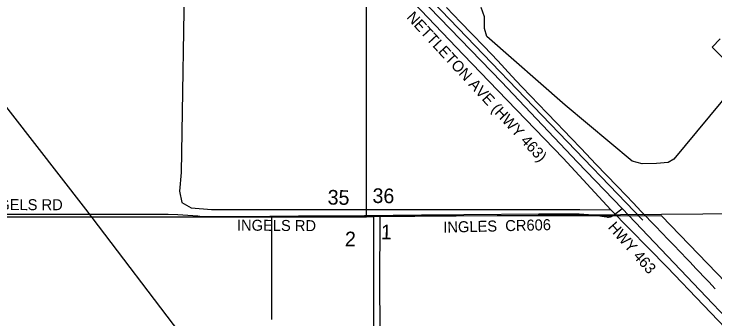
# Model space of a CAD drawing. Extents: x 1670563 to 1761545, y 515755 to 578944.
# Drawn here: x 1717674 to 1722466, y 533025 to 535106 of the extents above; entities that cross this region are included whole.
import ezdxf

# ---------------------------------------------------------------- set-up
doc = ezdxf.new("R2010")
doc.units = 0
for name, color, linetype in [('4_TwnRge', 7, 'Continuous'), ('5_sectionlines', 7, 'Continuous'), ('62_text', 7, 'Continuous'), ('LIMITS', 7, 'Continuous'), ('RR Tracks', 7, 'Continuous'), ('SHP_LINE', 7, 'Continuous'), ('STREETCL', 7, 'Continuous'), ('STRNAMES', 7, 'Continuous')]:
    doc.layers.add(name, color=color, linetype=linetype)

# ---------------------------------------------------------------- blocks, each defined once
blk = doc.blocks.new('CITY_LIMITS02')
at = {"layer": 'LIMITS'}
for p, q in [((1720133.6, 533723.3), (1719433.6, 533721.5)), ((1719433.6, 533721.5), (1719433.6, 533021.5))]:
    blk.add_line(p, q, dxfattribs=at)
for points in [[(1720186.9, 533726.2), (1719433.6, 533721.5)], [(1719433.6, 533721.5), (1719433.6, 533021.5)], [(1722101.2, 533728.6), (1720186.9, 533726.2)], [(1725619.7, 530087.6), (1722101.2, 533728.6)]]:
    blk.add_lwpolyline(points, dxfattribs=at)
blk = doc.blocks.new('RR TRACKS02')
at = {"layer": 'RR Tracks'}
for p, q in [((1720631.5, 535150.1), (1720678.7, 535101)), ((1720678.7, 535101), (1720726.7, 535050.3)), ((1720726.7, 535050.3), (1720803.3, 534970.9)), ((1720803.3, 534970.9), (1720887.3, 534883.9)), ((1720887.3, 534883.9), (1720980.7, 534786)), ((1720980.7, 534786), (1721076.2, 534682.2)), ((1721076.2, 534682.2), (1721143.9, 534612.4)), ((1721143.9, 534612.4), (1721209.1, 534544.3)), ((1721209.1, 534544.3), (1721258.2, 534493.2)), ((1721258.2, 534493.2), (1721319.4, 534429)), ((1721319.4, 534429), (1721381.8, 534364.4)), ((1721381.8, 534364.4), (1721434.4, 534308.8)), ((1721434.4, 534308.8), (1721479.7, 534261.8)), ((1721479.7, 534261.8), (1721550.1, 534187.9)), ((1721550.1, 534187.9), (1721651.7, 534082.3)), ((1721651.7, 534082.3), (1721723.8, 534007.2)), ((1721723.8, 534007.2), (1721796.7, 533931.4)), ((1721796.7, 533931.4), (1721857.7, 533867.3)), ((1721857.7, 533867.3), (1721905.8, 533817.5)), ((1721905.8, 533817.5), (1721962, 533759.4)), ((1721962, 533759.4), (1722062.2, 533655)), ((1722062.2, 533655), (1722100.4, 533614.8)), ((1722100.4, 533614.8), (1722148.2, 533565.7)), ((1722148.2, 533565.7), (1722176.7, 533535.5)), ((1722176.7, 533535.5), (1722234.2, 533475.3)), ((1722234.2, 533475.3), (1722267.9, 533439.9)), ((1722267.9, 533439.9), (1722293, 533413.9)), ((1722293, 533413.9), (1722337.8, 533367.2)), ((1722337.8, 533367.2), (1722360.6, 533344.4)), ((1722360.6, 533344.4), (1722387.2, 533315.1)), ((1722387.2, 533315.1), (1722423.6, 533277.7)), ((1722423.6, 533277.7), (1722467.5, 533231.8))]:
    blk.add_line(p, q, dxfattribs=at)

msp = doc.modelspace()

# ---------------------------------------------------------------- linework, layer by layer
at = {"layer": '4_TwnRge'}
msp.add_lwpolyline([(1714766.6, 533721.4), (1720083.7, 533721.1), (1720133.6, 533723.3), (1725191.1, 533766.2)], dxfattribs=at)
at = {"layer": '5_sectionlines'}
msp.add_line((1720083.7, 533721.1), (1720086.4, 537683), dxfattribs=at)
msp.add_lwpolyline([(1720176.8, 517754.9), (1720182.8, 523040.4), (1720130.2, 528390.8), (1720133.6, 533723.3)], dxfattribs=at)
at = {"layer": 'SHP_LINE'}
for points in [[(1716945, 538927), (1717499, 538359), (1718014, 537823), (1718693, 537111), (1720080, 535667), (1721972, 533700)], [(1716534, 536345), (1716546, 536123), (1716656, 535763), (1716958, 535332), (1717479, 534651), (1718163, 533775), (1718848, 532874), (1719368, 532244), (1719571, 531974), (1719701, 531778), (1719885, 531402), (1720057, 531046)], [(1721755, 533769), (1721429, 534123), (1720982, 534585), (1720746, 534827), (1720310, 535287), (1719979, 535628)], [(1718842, 535542), (1718816, 534025)], [(1722584, 534596), (1722184, 534116), (1722145, 534093), (1722067, 534086), (1721967, 534083), (1721899, 534103), (1721441, 534485), (1720907, 534953), (1720891, 535008), (1720891, 535086), (1720868, 535151)], [(1722502, 534936), (1722447, 534881), (1722577, 534751)], [(1718816, 534025), (1718806, 533897), (1718821, 533820), (1718886, 533784), (1719025, 533771), (1719558, 533773), (1719784, 533772), (1721542, 533772), (1721755, 533769)], [(1721755, 533769), (1722138, 533378), (1723630, 531822), (1724568, 530832), (1725321, 530047), (1726931, 528365), (1727244, 528033), (1727283, 527958), (1727301, 527835), (1727362, 527254), (1727431, 526925), (1727535, 526724), (1727681, 526504), (1728027, 526073), (1728202, 525853), (1728254, 525718), (1728235, 525608)]]:
    msp.add_lwpolyline(points, dxfattribs=at)
at = {"layer": 'STREETCL'}
for points in [[(1717072.9, 538715.7), (1717264.4, 538514.7), (1717510.3, 538264.3), (1717644.4, 538130.2), (1717873.6, 537900.7), (1718183.4, 537583.4), (1718347.1, 537415.1), (1718556.6, 537194.6), (1718908.4, 536828.7), (1719250.4, 536472.2), (1719637.9, 536070.3), (1720069.6, 535615.9), (1720515, 535151.1), (1721005.6, 534643.8), (1721526.6, 534096.2), (1721830.2, 533779.6)], [(1717547.4, 533740.3), (1717967.7, 533740.2), (1718469.2, 533740.2), (1718727.1, 533740.2), (1718795.2, 533738), (1718863.1, 533734), (1718930.9, 533728.1), (1718943.7, 533726.5), (1718956.5, 533725.4), (1718969.4, 533724.7), (1718982.2, 533724.4), (1718995.1, 533724.5), (1719228, 533724.5), (1719619.3, 533728.1), (1720069, 533731.7), (1720458.8, 533736.2), (1720749.9, 533739.1), (1721262.5, 533742), (1721507.4, 533742.9), (1721538.5, 533742.5), (1721569.5, 533741.2), (1721600.5, 533738.9), (1721631.4, 533735.7), (1721662.2, 533731.5), (1721692.8, 533726.4), (1721709.2, 533723.8), (1721725.7, 533721.6), (1721727.8, 533721.3), (1721729.8, 533721.1), (1721731.9, 533720.9), (1721734, 533720.8), (1721736.1, 533720.8), (1721738.2, 533720.8), (1721740.3, 533721), (1721742.4, 533721.2), (1721744.5, 533721.4), (1721746.6, 533721.8), (1721748.6, 533722.2), (1721750.7, 533722.7), (1721752.7, 533723.3), (1721754.7, 533723.9), (1721756.7, 533724.6), (1721758.7, 533725.4), (1721760.6, 533726.2), (1721762.5, 533727.1), (1721764.3, 533728.1), (1721766.2, 533729.1), (1721768, 533730.2), (1721769.7, 533731.4), (1721771.4, 533732.6), (1721773.1, 533733.9), (1721774.7, 533735.2), (1721776.3, 533736.6), (1721777.8, 533738), (1721830.2, 533779.6)], [(1722547.2, 533028.8), (1722452.2, 533127.5), (1721830.2, 533779.6)], [(1720174.9, 533732.9), (1720172.5, 533238.7), (1720186.1, 531788.3)]]:
    msp.add_lwpolyline(points, dxfattribs=at)

# ---------------------------------------------------------------- block references
for name in ['CITY_LIMITS02', 'RR TRACKS02']:
    msp.add_blockref(name, (0, 0), dxfattribs=at)

# ---------------------------------------------------------------- texts
at = {"layer": '62_text'}
for s, p in [('35', (1719817.6, 533806)), ('36', (1720124.2, 533817)), ('1', (1720181.4, 533569.1)), ('2', (1719935.6, 533521.5))]:
    msp.add_text(s, height=100, rotation=358.9328, dxfattribs=at).set_placement(p)
at = {"layer": 'STRNAMES'}
for s, rotation, p in [('NETTLETON AVE (HWY 463)', 312.7601, (1720353.3, 535080.5)), ('INGELS RD', 359.9323, (1717466.7, 533767.9)), ('INGELS RD', 359.5594, (1719198, 533628.2)), ('INGLES  CR606', 1.3962, (1720609.6, 533613.6)), ('HWY 463', 311.2618, (1721729.9, 533648.2))]:
    msp.add_text(s, height=75, rotation=rotation, dxfattribs=at).set_placement(p)

doc.saveas('drawing.dxf')
